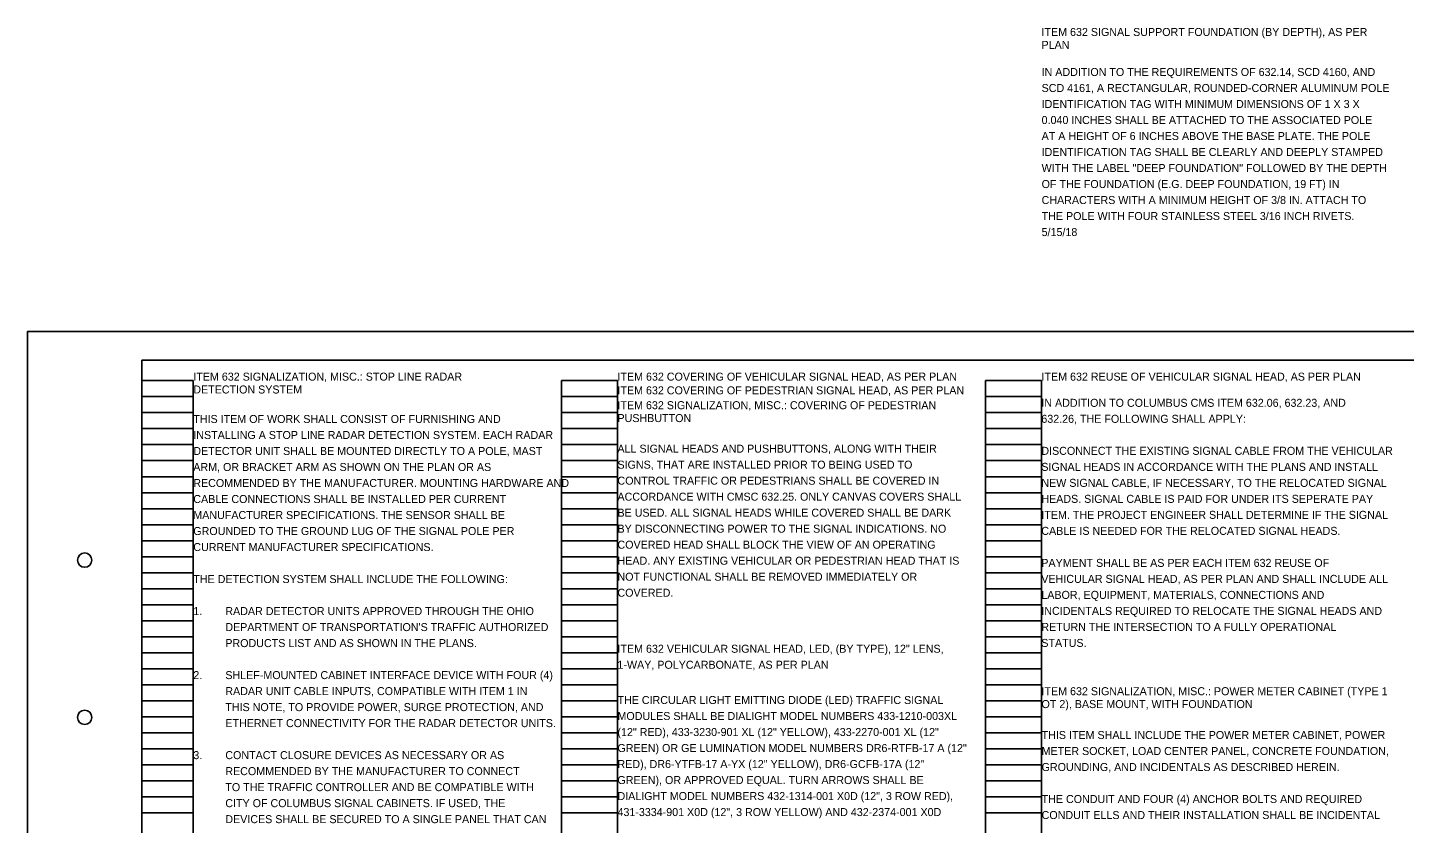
# Model space of a CAD drawing. Extents: x -50.5 to 43.5, y -13 to 19.8.
# Drawn here: x -0.51 to 23.58, y 5.89 to 19.81 of the extents above; entities that cross this region are included whole.
import ezdxf

# ---------------------------------------------------------------- set-up
doc = ezdxf.new("R2010")
doc.units = 0
for name, color, linetype in [('PF_P_Text', 7, 'Continuous'), ('SC_Scratch1', 7, 'Continuous'), ('SH_Cut_Line', 7, 'Continuous'), ('SH_Data', 7, 'Continuous'), ('SH_Text', 7, 'Continuous'), ('SN_P_Text', 7, 'Continuous')]:
    doc.layers.add(name, color=color, linetype=linetype)

msp = doc.modelspace()

# ---------------------------------------------------------------- linework, layer by layer
at = {"layer": 'PF_P_Text'}
msp.add_lwpolyline([(1.494, 13.992), (32.994, 13.992), (32.994, -7.008), (1.494, -7.008)], close=True, dxfattribs=at)
for centre in [(0.494, 10.492), (0.494, 7.742)]:
    msp.add_circle(centre, 0.125, dxfattribs=at)
at = {"layer": 'SC_Scratch1'}
for p, q in [((1.494, -6.528), (1.494, 13.632)), ((1.494, 13.632), (2.394, 13.632)), ((2.394, -6.528), (2.394, 13.632)), ((8.834, -6.528), (8.834, 13.632)), ((8.834, 13.632), (9.814, 13.632)), ((9.814, -6.528), (9.814, 13.632)), ((16.254, -6.528), (16.254, 13.632)), ((16.254, 13.632), (17.234, 13.632)), ((17.234, -6.528), (17.234, 13.632)), ((1.494, 13.352), (2.394, 13.352)), ((8.834, 13.352), (9.814, 13.352)), ((16.254, 13.352), (17.234, 13.352)), ((1.494, 13.072), (2.394, 13.072)), ((8.834, 13.072), (9.814, 13.072)), ((16.254, 13.072), (17.234, 13.072)), ((1.494, 12.792), (2.394, 12.792)), ((8.834, 12.792), (9.814, 12.792)), ((16.254, 12.792), (17.234, 12.792)), ((1.494, 12.512), (2.394, 12.512)), ((8.834, 12.512), (9.814, 12.512)), ((16.254, 12.512), (17.234, 12.512)), ((1.494, 12.232), (2.394, 12.232)), ((8.834, 12.232), (9.814, 12.232)), ((16.254, 12.232), (17.234, 12.232)), ((1.494, 11.952), (2.394, 11.952)), ((8.834, 11.952), (9.814, 11.952)), ((16.254, 11.952), (17.234, 11.952)), ((1.494, 11.672), (2.394, 11.672)), ((8.834, 11.672), (9.814, 11.672)), ((16.254, 11.672), (17.234, 11.672)), ((1.494, 11.392), (2.394, 11.392)), ((8.834, 11.392), (9.814, 11.392)), ((16.254, 11.392), (17.234, 11.392)), ((1.494, 11.112), (2.394, 11.112)), ((8.834, 11.112), (9.814, 11.112)), ((16.254, 11.112), (17.234, 11.112)), ((1.494, 10.832), (2.394, 10.832)), ((8.834, 10.832), (9.814, 10.832)), ((16.254, 10.832), (17.234, 10.832)), ((1.494, 10.552), (2.394, 10.552)), ((8.834, 10.552), (9.814, 10.552)), ((16.254, 10.552), (17.234, 10.552)), ((1.494, 10.272), (2.394, 10.272)), ((8.834, 10.272), (9.814, 10.272)), ((16.254, 10.272), (17.234, 10.272)), ((1.494, 9.992), (2.394, 9.992)), ((8.834, 9.992), (9.814, 9.992)), ((16.254, 9.992), (17.234, 9.992)), ((1.494, 9.712), (2.394, 9.712)), ((8.834, 9.712), (9.814, 9.712)), ((16.254, 9.712), (17.234, 9.712)), ((1.494, 9.432), (2.394, 9.432)), ((8.834, 9.432), (9.814, 9.432)), ((16.254, 9.432), (17.234, 9.432)), ((1.494, 9.152), (2.394, 9.152)), ((8.834, 9.152), (9.814, 9.152)), ((16.254, 9.152), (17.234, 9.152)), ((1.494, 8.872), (2.394, 8.872)), ((8.834, 8.872), (9.814, 8.872)), ((16.254, 8.872), (17.234, 8.872)), ((1.494, 8.592), (2.394, 8.592)), ((8.834, 8.592), (9.814, 8.592)), ((16.254, 8.592), (17.234, 8.592)), ((1.494, 8.312), (2.394, 8.312)), ((8.834, 8.312), (9.814, 8.312)), ((16.254, 8.312), (17.234, 8.312)), ((1.494, 8.032), (2.394, 8.032)), ((8.834, 8.032), (9.814, 8.032)), ((16.254, 8.032), (17.234, 8.032)), ((1.494, 7.752), (2.394, 7.752)), ((8.834, 7.752), (9.814, 7.752)), ((16.254, 7.752), (17.234, 7.752)), ((1.494, 7.472), (2.394, 7.472)), ((8.834, 7.472), (9.814, 7.472)), ((16.254, 7.472), (17.234, 7.472)), ((1.494, 7.192), (2.394, 7.192)), ((8.834, 7.192), (9.814, 7.192)), ((16.254, 7.192), (17.234, 7.192)), ((1.494, 6.912), (2.394, 6.912)), ((8.834, 6.912), (9.814, 6.912)), ((16.254, 6.912), (17.234, 6.912)), ((1.494, 6.632), (2.394, 6.632)), ((8.834, 6.632), (9.814, 6.632)), ((16.254, 6.632), (17.234, 6.632)), ((1.494, 6.352), (2.394, 6.352)), ((8.834, 6.352), (9.814, 6.352)), ((16.254, 6.352), (17.234, 6.352)), ((1.494, 6.072), (2.394, 6.072)), ((8.834, 6.072), (9.814, 6.072)), ((16.254, 6.072), (17.234, 6.072))]:
    msp.add_line(p, q, dxfattribs=at)
at = {"layer": 'SH_Cut_Line'}
msp.add_lwpolyline([(-0.506, -7.508), (33.494, -7.508), (33.494, 14.492), (-0.506, 14.492)], close=True, dxfattribs=at)

# ---------------------------------------------------------------- texts
at = {"layer": 'SH_Data'}
for s, p in [('ITEM 632 SIGNAL SUPPORT FOUNDATION (BY DEPTH), AS PER ', (17.232, 19.661)), ('PLAN', (17.232, 19.436)), ('ITEM 632 COVERING OF VEHICULAR SIGNAL HEAD, AS PER PLAN', (9.814, 13.632)), ('ITEM 632 REUSE OF VEHICULAR SIGNAL HEAD, AS PER PLAN', (17.232, 13.632))]:
    msp.add_text(s, height=0.14, dxfattribs=at).set_placement(p)
for s, rotation, p in [('ITEM 632 SIGNALIZATION, MISC.: STOP LINE RADAR ', 360, (2.394, 13.632)), ('DETECTION SYSTEM', 360, (2.394, 13.407)), ('ITEM 632 SIGNALIZATION, MISC.: POWER METER CABINET (TYPE 1 ', 0, (17.232, 8.129)), ('OT 2), BASE MOUNT, WITH FOUNDATION', 0, (17.232, 7.904))]:
    msp.add_text(s, height=0.14, rotation=rotation, dxfattribs=at).set_placement(p)
at = {"layer": 'SH_Text'}
for s, p in [('IN ADDITION TO THE REQUIREMENTS OF 632.14, SCD 4160, AND ', (17.234, 18.961)), ('SCD 4161, A RECTANGULAR, ROUNDED-CORNER ALUMINUM POLE ', (17.234, 18.681)), ('IDENTIFICATION TAG WITH MINIMUM DIMENSIONS OF 1 X 3 X ', (17.234, 18.401)), ('0.040 INCHES SHALL BE ATTACHED TO THE ASSOCIATED POLE ', (17.234, 18.121)), ('AT A HEIGHT OF 6 INCHES ABOVE THE BASE PLATE. THE POLE ', (17.234, 17.841)), ('IDENTIFICATION TAG SHALL BE CLEARLY AND DEEPLY STAMPED ', (17.234, 17.561)), ('WITH THE LABEL "DEEP FOUNDATION" FOLLOWED BY THE DEPTH ', (17.234, 17.281)), ('OF THE FOUNDATION (E.G. DEEP FOUNDATION, 19 FT) IN ', (17.234, 17.001)), ('CHARACTERS WITH A MINIMUM HEIGHT OF 3/8 IN. ATTACH TO ', (17.234, 16.721)), ('THE POLE WITH FOUR STAINLESS STEEL 3/16 INCH RIVETS.', (17.234, 16.441)), ('5/15/18', (17.234, 16.161)), ('ITEM 632 COVERING OF PEDESTRIAN SIGNAL HEAD, AS PER PLAN', (9.814, 13.392)), ('ITEM 632 SIGNALIZATION, MISC.: COVERING OF PEDESTRIAN ', (9.814, 13.132)), ('IN ADDITION TO COLUMBUS CMS ITEM 632.06, 632.23, AND ', (17.229, 13.174)), ('PUSHBUTTON', (9.814, 12.907)), ('632.26, THE FOLLOWING SHALL APPLY:', (17.229, 12.894)), ('ALL SIGNAL HEADS AND PUSHBUTTONS, ALONG WITH THEIR ', (9.814, 12.372)), ('DISCONNECT THE EXISTING SIGNAL CABLE FROM THE VEHICULAR ', (17.229, 12.334)), ('SIGNS, THAT ARE INSTALLED PRIOR TO BEING USED TO ', (9.814, 12.092)), ('SIGNAL HEADS IN ACCORDANCE WITH THE PLANS AND INSTALL ', (17.229, 12.054)), ('CONTROL TRAFFIC OR PEDESTRIANS SHALL BE COVERED IN ', (9.814, 11.812)), ('NEW SIGNAL CABLE, IF NECESSARY, TO THE RELOCATED SIGNAL ', (17.229, 11.774)), ('ACCORDANCE WITH CMSC 632.25. ONLY CANVAS COVERS SHALL ', (9.814, 11.532)), ('HEADS. SIGNAL CABLE IS PAID FOR UNDER ITS SEPERATE PAY ', (17.229, 11.494)), ('BE USED. ALL SIGNAL HEADS WHILE COVERED SHALL BE DARK ', (9.814, 11.252)), ('ITEM. THE PROJECT ENGINEER SHALL DETERMINE IF THE SIGNAL ', (17.229, 11.214)), ('BY DISCONNECTING POWER TO THE SIGNAL INDICATIONS. NO ', (9.814, 10.972)), ('CABLE IS NEEDED FOR THE RELOCATED SIGNAL HEADS.', (17.229, 10.934)), ('COVERED HEAD SHALL BLOCK THE VIEW OF AN OPERATING ', (9.814, 10.692)), ('HEAD. ANY EXISTING VEHICULAR OR PEDESTRIAN HEAD THAT IS ', (9.814, 10.412)), ('PAYMENT SHALL BE AS PER EACH ITEM 632 REUSE OF ', (17.229, 10.374)), ('NOT FUNCTIONAL SHALL BE REMOVED IMMEDIATELY OR ', (9.814, 10.132)), ('VEHICULAR SIGNAL HEAD, AS PER PLAN AND SHALL INCLUDE ALL ', (17.229, 10.094)), ('COVERED. ', (9.814, 9.852)), ('LABOR, EQUIPMENT, MATERIALS, CONNECTIONS AND ', (17.229, 9.814)), ('INCIDENTALS REQUIRED TO RELOCATE THE SIGNAL HEADS AND ', (17.229, 9.534)), ('RETURN THE INTERSECTION TO A FULLY OPERATIONAL ', (17.229, 9.254)), ('ITEM 632 VEHICULAR SIGNAL HEAD, LED, (BY TYPE), 12" LENS, ', (9.814, 8.872)), ('STATUS. ', (17.229, 8.974)), ('1-WAY, POLYCARBONATE, AS PER PLAN', (9.814, 8.592)), ('THE CIRCULAR LIGHT EMITTING DIODE (LED) TRAFFIC SIGNAL ', (9.814, 7.975)), ('MODULES SHALL BE DIALIGHT MODEL NUMBERS 433-1210-003XL ', (9.814, 7.695)), ('(12" RED), 433-3230-901 XL (12" YELLOW), 433-2270-001 XL (12" ', (9.814, 7.415)), ('GREEN) OR GE LUMINATION MODEL NUMBERS DR6-RTFB-17 A (12" ', (9.814, 7.135)), ('RED), DR6-YTFB-17 A-YX (12" YELLOW), DR6-GCFB-17A (12" ', (9.814, 6.855)), ('GREEN), OR APPROVED EQUAL. TURN ARROWS SHALL BE ', (9.814, 6.575)), ('DIALIGHT MODEL NUMBERS 432-1314-001 X0D (12", 3 ROW RED), ', (9.814, 6.295)), ('431-3334-901 X0D (12", 3 ROW YELLOW) AND 432-2374-001 X0D ', (9.814, 6.015))]:
    msp.add_text(s, height=0.14, dxfattribs=at).set_placement(p)
for s, p in [('THIS ITEM OF WORK SHALL CONSIST OF FURNISHING AND ', (2.394, 12.891)), ('INSTALLING A STOP LINE RADAR DETECTION SYSTEM. EACH RADAR ', (2.394, 12.611)), ('DETECTOR UNIT SHALL BE MOUNTED DIRECTLY TO A POLE, MAST ', (2.394, 12.331)), ('ARM, OR BRACKET ARM AS SHOWN ON THE PLAN OR AS ', (2.394, 12.051)), ('RECOMMENDED BY THE MANUFACTURER. MOUNTING HARDWARE AND ', (2.394, 11.771)), ('CABLE CONNECTIONS SHALL BE INSTALLED PER CURRENT ', (2.394, 11.491)), ('MANUFACTURER SPECIFICATIONS. THE SENSOR SHALL BE ', (2.394, 11.211)), ('GROUNDED TO THE GROUND LUG OF THE SIGNAL POLE PER ', (2.394, 10.931)), ('CURRENT MANUFACTURER SPECIFICATIONS.', (2.394, 10.651)), ('THE DETECTION SYSTEM SHALL INCLUDE THE FOLLOWING:', (2.394, 10.091)), ('1.', (2.394, 9.531)), ('RADAR DETECTOR UNITS APPROVED THROUGH THE OHIO ', (2.954, 9.531)), ("DEPARTMENT OF TRANSPORTATION'S TRAFFIC AUTHORIZED ", (2.954, 9.251)), ('PRODUCTS LIST AND AS SHOWN IN THE PLANS.', (2.954, 8.971)), ('2.', (2.394, 8.411)), ('SHLEF-MOUNTED CABINET INTERFACE DEVICE WITH FOUR (4) ', (2.954, 8.411)), ('RADAR UNIT CABLE INPUTS, COMPATIBLE WITH ITEM 1 IN ', (2.954, 8.131)), ('THIS NOTE, TO PROVIDE POWER, SURGE PROTECTION, AND ', (2.954, 7.851)), ('ETHERNET CONNECTIVITY FOR THE RADAR DETECTOR UNITS. ', (2.954, 7.571)), ('3.', (2.394, 7.011)), ('CONTACT CLOSURE DEVICES AS NECESSARY OR AS ', (2.954, 7.011)), ('RECOMMENDED BY THE MANUFACTURER TO CONNECT ', (2.954, 6.731)), ('TO THE TRAFFIC CONTROLLER AND BE COMPATIBLE WITH ', (2.954, 6.451)), ('CITY OF COLUMBUS SIGNAL CABINETS. IF USED, THE ', (2.954, 6.171)), ('DEVICES SHALL BE SECURED TO A SINGLE PANEL THAT CAN ', (2.954, 5.891))]:
    msp.add_text(s, height=0.14, rotation=360, dxfattribs=at).set_placement(p)
at = {"layer": 'SN_P_Text'}
for s, p in [('THIS ITEM SHALL INCLUDE THE POWER METER CABINET, POWER ', (17.234, 7.363)), ('METER SOCKET, LOAD CENTER PANEL, CONCRETE FOUNDATION, ', (17.234, 7.083)), ('GROUNDING, AND INCIDENTALS AS DESCRIBED HEREIN.', (17.234, 6.803)), ('THE CONDUIT AND FOUR (4) ANCHOR BOLTS AND REQUIRED ', (17.234, 6.243)), ('CONDUIT ELLS AND THEIR INSTALLATION SHALL BE INCIDENTAL ', (17.234, 5.963))]:
    msp.add_text(s, height=0.14, rotation=0, dxfattribs=at).set_placement(p)

doc.saveas('drawing.dxf')
